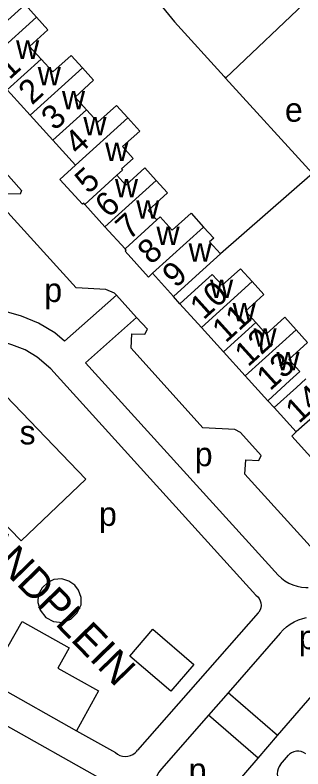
# Model space of a CAD drawing. Extents: x 158356 to 159894, y 383831 to 385260.
# Drawn here: x 159000.7 to 159048.8, y 384085.1 to 384210.9 of the extents above; entities that cross this region are included whole.
import ezdxf

# ---------------------------------------------------------------- set-up
doc = ezdxf.new("R2010")
doc.units = 0
for name, color, linetype in [('BLT_Basislijn', 7, 'Continuous'), ('BLT_Bebouwing', 7, 'Continuous'), ('BLT_Centroide', 7, 'Continuous'), ('BLT_Huisnummer', 7, 'Continuous'), ('BLT_Huisnummer_ tussenligend', 7, 'Continuous'), ('BLT_Onderverdeling_panden', 7, 'Continuous'), ('BLT_Straatnaam', 7, 'Continuous')]:
    doc.layers.add(name, color=color, linetype=linetype)

msp = doc.modelspace()

# ---------------------------------------------------------------- linework, layer by layer
at = {"layer": 'BLT_Basislijn'}
for p, q in [((159050.16, 384213.98), (159035.82, 384200.38)), ((159035.82, 384200.38), (159050.33, 384184.44)), ((159050.33, 384184.44), (159034.97, 384171.04)), ((159017.62, 384164.14), (159008.97, 384156.46)), ((159020.98, 384160.44), (159017.62, 384164.14)), ((159028.23, 384162.71), (159027.15, 384163.95)), ((159020.98, 384160.44), (159012.46, 384152.88)), ((159012.46, 384152.88), (159044.6, 384117.43)), ((159006.64, 384151.86), (159040.89, 384114.07)), ((159043.95, 384145.4), (159042.87, 384146.54)), ((158953.11, 384118.31), (159015.76, 384083.03)), ((159041.31, 384111.14), (159021.14, 384088.2)), ((159044.98, 384107.73), (159036.27, 384097.8)), ((159044.52, 384090.67), (159057.26, 384105.41)), ((158996.21, 384099.78), (159010.97, 384091.47)), ((159036.27, 384097.8), (159032.97, 384094.05)), ((159044.52, 384090.67), (159036.27, 384097.8)), ((159032.97, 384094.05), (159025.12, 384085.11)), ((159041.26, 384086.88), (159032.97, 384094.05)), ((159010.97, 384091.47), (159017.46, 384087.81)), ((159041.26, 384086.88), (159044.52, 384090.67)), ((159029.22, 384072.94), (159041.26, 384086.88)), ((159045.02, 384085.86), (159046.34, 384087.39))]:
    msp.add_line(p, q, dxfattribs=at)
for points in [[(159017.16, 384222.26), (159017.6, 384221.7), (159027.31, 384209.73), (159035.61, 384200.61), (159035.82, 384200.38)], [(158997.83, 384186), (159001.78, 384181.62), (159001.54, 384181), (158999.06, 384181.08)], [(159010.91, 384165.35), (158998.93, 384178.56), (158999.06, 384181.08)], [(159017.62, 384164.14), (159017.29, 384164.5), (159015.86, 384165.11), (159010.91, 384165.35)], [(159008.97, 384156.46), (159007.32, 384157.89), (159004.61, 384159.5), (159001.77, 384160.62), (158998.86, 384161.47), (158995.99, 384161.86)], [(159032.06, 384142.03), (159020.1, 384155.32), (159020.2, 384157.72), (159022.34, 384157.65), (159022.79, 384158.46), (159020.98, 384160.44)], [(159006.64, 384151.86), (159004.38, 384153.82), (159002.4, 384155), (159000.15, 384155.88), (158997.82, 384156.56), (158995.47, 384156.88), (158993.12, 384156.87), (158978.76, 384154.46), (158976.27, 384153.81), (158974.11, 384152.86), (158971.74, 384150.94), (158968.65, 384146.8)], [(159051.05, 384121.06), (159039.06, 384134.3), (159039.2, 384136.68), (159041.41, 384136.56), (159041.81, 384137.39), (159038.35, 384141.23), (159037.38, 384141.72), (159032.06, 384142.03)], [(159044.6, 384117.43), (159045.15, 384116.92), (159045.74, 384116.48), (159046.39, 384116.11), (159047.07, 384115.81), (159047.77, 384115.58), (159048.5, 384115.43), (159049.24, 384115.36), (159049.63, 384115.36)], [(159040.89, 384114.07), (159041.2, 384113.82), (159041.46, 384113.52), (159041.64, 384113.17), (159041.75, 384112.79), (159041.79, 384112.39), (159041.74, 384112), (159041.62, 384111.62), (159041.42, 384111.28), (159041.31, 384111.14)], [(159044.98, 384107.73), (159045.48, 384108.3), (159046.04, 384108.82), (159046.65, 384109.27), (159047.31, 384109.66), (159048, 384109.97), (159048.72, 384110.21), (159049.35, 384110.36)], [(158996.21, 384099.78), (159001.86, 384109.69), (159009.71, 384105.3), (159007.85, 384101.91), (159014.65, 384098.11), (159010.97, 384091.47)], [(159023.7, 384108.39), (159030.52, 384102.53), (159026.68, 384098.05), (159019.85, 384103.92), (159023.7, 384108.39)], [(159017.46, 384087.81), (159017.82, 384087.55), (159018.21, 384087.35), (159018.64, 384087.22), (159019.09, 384087.17), (159019.53, 384087.21), (159019.96, 384087.32), (159020.36, 384087.51), (159020.73, 384087.76), (159021.04, 384088.08), (159021.14, 384088.2)], [(159049.22, 384087.62), (159048.87, 384087.84), (159048.48, 384087.99), (159048.08, 384088.06), (159047.66, 384088.05), (159047.26, 384087.97), (159046.87, 384087.8), (159046.53, 384087.57), (159046.34, 384087.39)], [(159025.12, 384085.11), (159024.71, 384084.55), (159024.37, 384083.95), (159024.09, 384083.31), (159023.89, 384082.65), (159023.77, 384081.97), (159023.73, 384081.28), (159023.77, 384080.55)], [(159045.02, 384085.86), (159044.77, 384085.51), (159044.6, 384085.13), (159044.49, 384084.72), (159044.47, 384084.29), (159044.53, 384083.87), (159044.66, 384083.47), (159044.87, 384083.1), (159045.03, 384082.9)]]:
    msp.add_lwpolyline(points, dxfattribs=at)
for points in [[(158995.11, 384151.5), (159012.51, 384133.45), (159001.73, 384123.15), (158984.32, 384141.02)], [(159005.21, 384115.31), (159004.57, 384114.15), (159004.52, 384112.87), (159004.9, 384111.58), (159005.83, 384110.35), (159007.09, 384109.72), (159008.59, 384109.52), (159010, 384110.09), (159011.08, 384111.12), (159011.72, 384112.46), (159011.72, 384113.71), (159011.29, 384114.9), (159010.67, 384115.75), (159009.69, 384116.42), (159008.5, 384116.8), (159007.17, 384116.7), (159006.14, 384116.21)]]:
    msp.add_lwpolyline(points, close=True, dxfattribs=at)
at = {"layer": 'BLT_Bebouwing'}
for p, q in [((159007, 384190.01), (159003.21, 384194.18)), ((159010.79, 384185.84), (159007, 384190.01)), ((159015.71, 384175.56), (159012.32, 384179.3)), ((159019.05, 384171.87), (159015.71, 384175.56)), ((159027.15, 384163.95), (159023.65, 384167.8)), ((159028.23, 384162.71), (159031.81, 384158.75)), ((159031.81, 384158.75), (159035.49, 384154.69)), ((159035.49, 384154.69), (159039.13, 384150.67)), ((159039.13, 384150.67), (159042.87, 384146.54)), ((159047.65, 384141.32), (159043.95, 384145.4))]:
    msp.add_line(p, q, dxfattribs=at)
for points in [[(158995.72, 384209.68), (158997.57, 384210.35), (158998.88, 384209.5), (159000.03, 384210.53), (159002.36, 384212.65), (159004.27, 384210.55)], [(159004.27, 384210.55), (159006.18, 384208.44), (159003.11, 384205.66), (159005.05, 384203.53)], [(159005.05, 384203.53), (159006.99, 384201.39), (159010.04, 384204.16), (159011.93, 384202.08)], [(159011.93, 384202.08), (159013.81, 384200), (159010.72, 384197.19), (159012.62, 384195.1)], [(159003.21, 384194.18), (159000, 384197.72), (158999.39, 384198.39)], [(159012.62, 384195.1), (159014.51, 384193.01), (159017.62, 384195.82), (159019.51, 384193.74)], [(159019.51, 384193.74), (159021.51, 384191.53), (159018.64, 384188.93), (159020.41, 384186.97), (159018.47, 384185.21), (159018.63, 384185.03), (159017.67, 384184.16)], [(159012.32, 384179.3), (159012.15, 384179.49), (159011.96, 384179.32), (159008.18, 384183.47), (159010.79, 384185.84)], [(159017.67, 384184.16), (159019.17, 384182.51), (159022.34, 384185.38), (159024.23, 384183.29)], [(159024.23, 384183.29), (159026.13, 384181.2), (159022.93, 384178.3), (159024.38, 384176.71)], [(159024.38, 384176.71), (159024.92, 384177.2), (159026.93, 384174.99), (159030.07, 384177.84), (159032.17, 384175.52)], [(159032.17, 384175.52), (159033.86, 384173.66), (159033.16, 384173.04), (159034.97, 384171.04)], [(159023.65, 384167.8), (159022.96, 384167.17), (159019.07, 384171.47), (159019.26, 384171.64), (159019.05, 384171.87)], [(159034.97, 384171.04), (159030.85, 384167.3), (159027.15, 384163.95)], [(159040.27, 384166.41), (159038.33, 384168.55), (159035.28, 384165.79), (159033.6, 384167.61), (159031.93, 384166.07), (159028.23, 384162.71)], [(159040.27, 384166.41), (159042.21, 384164.27), (159039.14, 384161.48), (159040.87, 384159.57)], [(159040.87, 384159.57), (159042.61, 384157.66), (159045.72, 384160.47), (159047.62, 384158.37)], [(159042.87, 384146.54), (159046.57, 384149.9), (159048.22, 384151.39), (159046.39, 384153.41), (159049.53, 384156.26), (159047.62, 384158.37)], [(159043.95, 384145.4), (159047.66, 384148.76), (159049.26, 384150.21)], [(159050.96, 384136.43), (159050.73, 384136.68), (159050.59, 384136.55), (159046.89, 384140.63), (159047.65, 384141.32)]]:
    msp.add_lwpolyline(points, dxfattribs=at)
at = {"layer": 'BLT_Onderverdeling_panden'}
for p, q in [((159004.27, 384210.55), (158995.54, 384202.63)), ((159005.05, 384203.53), (158999.39, 384198.39)), ((159011.93, 384202.08), (159003.21, 384194.18)), ((159012.62, 384195.1), (159007, 384190.01)), ((159019.51, 384193.74), (159010.79, 384185.84)), ((159017.67, 384184.16), (159012.32, 384179.3)), ((159024.23, 384183.29), (159015.71, 384175.56)), ((159024.38, 384176.71), (159019.05, 384171.87)), ((159032.17, 384175.52), (159023.65, 384167.8)), ((159040.27, 384166.41), (159031.81, 384158.75)), ((159040.87, 384159.57), (159035.49, 384154.69)), ((159047.62, 384158.37), (159039.13, 384150.67)), ((159056.24, 384148.99), (159047.65, 384141.32))]:
    msp.add_line(p, q, dxfattribs=at)

# ---------------------------------------------------------------- texts
at = {"layer": 'BLT_Centroide'}
for s, p in [('w', (159000.86, 384203.58)), ('w', (159004.48, 384199.16)), ('w', (159008.52, 384195.17)), ('e', (159045.75, 384193.09)), ('w', (159012.1, 384190.81)), ('w', (159015.73, 384186.53)), ('w', (159017.37, 384180.47)), ('w', (159020.92, 384176.92)), ('w', (159024.3, 384172.5)), ('w', (159029.66, 384169.75)), ('w', (159033.24, 384163.66)), ('p', (159005.58, 384163.01)), ('w', (159037.02, 384159.77)), ('w', (159040.5, 384155.56)), ('w', (159044.33, 384151.62)), ('s', (159001.45, 384139.25)), ('p', (159030.7, 384135.61)), ('p', (159014.71, 384125.65)), ('p', (159048.07, 384105.07)), ('p', (159029.68, 384082.92))]:
    msp.add_text(s, height=4, dxfattribs=at).set_placement(p)
at = {"layer": 'BLT_Huisnummer'}
for s, p in [('1', (158999.74, 384199.98)), ('3', (159007.32, 384191.46)), ('5', (159012.93, 384180.9)), ('7', (159019.73, 384173.22)), ('9', (159027.53, 384165.21)), ('10', (159032.15, 384159.9)), ('13', (159043.26, 384148.07)), ('14', (159048.09, 384142.61))]:
    msp.add_text(s, height=4, rotation=42.1914, dxfattribs=at).set_placement(p)
at = {"layer": 'BLT_Huisnummer_ tussenligend'}
for s, p in [('2', (159003.51, 384195.77)), ('4', (159011.22, 384187.34)), ('6', (159016.3, 384176.89)), ('8', (159023.4, 384169.1)), ('11', (159035.85, 384156.06)), ('12', (159039.59, 384152.07))]:
    msp.add_text(s, height=4, rotation=42.1914, dxfattribs=at).set_placement(p)
at = {"layer": 'BLT_Straatnaam'}
msp.add_text('GELDERLANDPLEIN', height=5, rotation=314.1951, dxfattribs=at).set_placement((158972.54, 384144.95))

doc.saveas('drawing.dxf')
